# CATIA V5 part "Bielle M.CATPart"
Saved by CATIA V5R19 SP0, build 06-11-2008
Part number: Bielle M
Bounding box of the stored display mesh (mm): x -140 to 140, y -300 to -77.996, z -1349.993 to -50
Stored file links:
  G:\EU_thinkMotion\CFAO_2010\MMS_groupe3\MMS_groupe3\rdalborgo\rdalborgo\Bielle M.CATPart
  G:\EU_thinkMotion\CFAO_2010\MMS_groupe3\MMS_groupe3\rdalborgo\rdalborgo\Bielle P.CATPart
  G:\EU_thinkMotion\CFAO_2010\MMS_groupe3\MMS_groupe3\rdalborgo\rdalborgo\rdalborgo.CATProduct
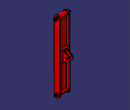
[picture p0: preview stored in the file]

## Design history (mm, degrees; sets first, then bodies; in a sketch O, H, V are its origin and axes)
External parameters (linked from other documents)
  `External.Largeur bielle` = 210 mm
Set1
  Plane1: linked copy from another document
  Point1 "A bielle": linked copy from another document
  Point2 "D bielle": linked copy from another document
  Plane2: linked copy from another document
  Point3 "B verin para": linked copy from another document
  Line1: linked copy from another document
  Point4: linked copy from another document
  Plane3: linked copy from another document
Body1 (main body)
  Sketch1 on Plane1, origin (0, 0, 0), H (0, 1, 0), V (0, 0, 1)
    circle A1 centre (-250, -100) radius 15
    point P1 (-250, -100)
    arc A2 centre (-250, -100) radius 50 from (-200.0003, -99.8329) to (-300, -100) ccw
    point P2 (-250, -100)
    reference projected point E1 (-250, -100) from Point1
    circle A3 centre (-245.9904, -1299.9933) radius 15
    point P3 (-245.9904, -1299.9933)
    point P4 (-245.9904, -1299.9933)
    reference projected point E2 (-245.9904, -1299.9933) from Point2
    line L1 (-300, -100) -> (-295.9904, -1299.9933)
    point P5 (-300, -100)
    line L2 (-195.9904, -1299.9933) -> (-200.0003, -99.8329)
    point P7 (-195.9904, -1299.9933)
    point P8 (-200.0003, -99.8329)
    point P9 (-200.0003, -99.8329)
    arc A4 centre (-245.9904, -1299.9933) radius 50 from (-295.9904, -1299.9933) to (-195.9904, -1299.9933) ccw
    point P10 (-195.9904, -1299.9933)
    radius A1 = 15
    radius A2 = 50
    radius A3 = 15
    radius A4 = 50
    coincidence: P2 P1, P1 E1, P4 P3, P3 E2, P5 A2, P8 A2, P7 P10, P8 P9
    tangency: L2 A2
  Pad1: profile Sketch1, direction (1, 0, 0), length 95, mirrored extent
  Sketch2 on Plane1, origin (0, 0, 0), H (0, 1, 0), V (0, 0, 1)
    arc A1 centre (-250, -100) radius 35 from (-215, -100) to (-260, -133.541) ccw
    point P1 (-250, -100)
    reference projected point E1 (-250, -100) from Point1
    arc A2 centre (-245.9904, -1299.9933) radius 35 from (-210.9904, -1299.9933) to (-240, -1265.5098) ccw
    point P2 (-245.9904, -1299.9933)
    reference projected point E2 (-245.9904, -1299.9933) from Point2
    line L1 (-260, -1267.9194) -> (-260, -133.541)
    point P3 (-260, -1267.9194)
    line L2 (-240, -133.541) -> (-240, -1265.5098)
    point P5 (-240, -133.541)
    point P6 (-240, -1265.5098)
    reference projected point E3 (-250, -100) from Point1
    arc A3 centre (-250, -100) radius 35 from (-240, -133.541) to (-215, -100) ccw
    point P7 (-215, -100)
    point P8 (-215, -100)
    point P9 (-210.9904, -1299.9933)
    point P10 (-210.9904, -1299.9933)
    arc A4 centre (-245.9904, -1299.9933) radius 35 from (-260, -1267.9194) to (-210.9904, -1299.9933) ccw
    radius A1 = 35
    radius A2 = 35
    distance L1 L2 = 20
    distance L1 E3 = 10
    coincidence: P1 E1, P2 E2, P3 A2, P5 A1, P6 A2, A1 A3, P7 P8, P9 P10
    vertical: L1 V, L2 V
  Pocket1: profile Sketch2, direction (-1, 0, 0), length 75, mirrored extent, outer side
  SolidCombine1: FirstComponentProfile Sketch5, FirstComponentDirection Sketch5, SecondComponentProfile Sketch6, SecondComponentDirection Sketch6
  Sketch3 on Plane2, origin (0, 0, 0), H (0, 1, 0), V (0, 0, 1)
    circle A1 centre (-117.9959, -699.5623) radius 10
    point P1 (-117.9959, -699.5623)
    reference projected point E1 (-117.9959, -699.5623) from Point3
    radius A1 = 10
    coincidence: P1 E1
  Pocket2: profile Sketch3, direction (-1, 0, 0), length 105 {= `External.Largeur bielle` /2}, mirrored extent
  Sketch4 on Plane2, origin (0, 0, 0), H (0, 1, 0), V (0, 0, 1)
    circle A1 centre (-250, -100) radius 15
    point P1 (-250, -100)
    circle A2 centre (-250, -100) radius 25
    point P2 (-250, -100)
    circle A3 centre (-245.9904, -1299.9933) radius 15
    circle A4 centre (-245.9904, -1299.9933) radius 25
    point P3 (-245.9904, -1299.9933)
    point P4 (-245.9904, -1299.9933)
    reference projected point E1 (-250, -100) from Point1
    reference projected point E2 (-245.9904, -1299.9933) from Point2
    radius A1 = 15
    radius A2 = 25
    radius A3 = 15
    radius A4 = 25
    coincidence: P2 P1, P4 P3, P2 E1, P4 E2
  Pad2: profile Sketch4, direction (1, 0, 0), length 105 {= `External.Largeur bielle` /2}, mirrored extent
  Sketch5 on Plane3, origin (0, -0.0014, -699.168), H (1, 0, 0), V (0, -1, -0.0033)
    line L1 (75, 197.9952) -> (75, 232.9952)
    line L2 (75, 232.9952) -> (-75, 232.9952)
    line L3 (-75, 232.9952) -> (-75, 197.9952)
    line L4 (-75, 197.9952) -> (-35, 197.9952)
    line L5 (-35, 197.9952) -> (-35, 47.9952)
    line L6 (-35, 47.9952) -> (-20, 47.9952)
    line L7 (-20, 47.9952) -> (-20, 197.9952)
    point P8 (-20, 197.9952)
    line L8 (-20, 197.9952) -> (20, 197.9952)
    line L9 (20, 197.9952) -> (20, 47.9952)
    point P10 (20, 47.9952)
    line L10 (20, 47.9952) -> (35, 47.9952)
    line L11 (35, 47.9952) -> (35, 197.9952)
    point P12 (35, 197.9952)
    line L12 (35, 197.9952) -> (75, 197.9952)
    reference projected point E1 (0, 247.9952) from Point4
    reference projected point E2 (0, 247.9952) from Point4
    reference projected point E3 (0, 247.9952) from Point4
    distance L2 E1 = 15
    distance L2 L12 = 35
    distance L3 L1 = 150 {= `External.Largeur bielle` -60mm}
    distance L3 E2 = 75 {= `External.Largeur bielle` /2-30mm}
    distance L5 L7 = 15
    distance L9 L11 = 15
    distance L6 L8 = 150
    distance L7 L9 = 40
    distance L7 E3 = 20
    vertical: L1 V, L3 V, L5 V, L7 V, L9 V, L11 V
    horizontal: L2 H, L4 H, L6 H, L8 H, L10 H, L12 H
    coincidence: P8 L4, P10 L6, P12 L4
  Sketch6 on Plane2, origin (0, 0, 0), H (0, 1, 0), V (0, 0, 1)
    arc A1 centre (-117.9959, -699.5623) radius 40 from (-77.9959, -699.5623) to (-96.2794, -665.9707) ccw
    point P1 (-117.9959, -699.5623)
    reference projected point E1 (-117.9959, -699.5623) from Point3
    line L1 (-198.3293, -599.9967) -> (-96.2794, -665.9707)
    point P3 (-96.2794, -665.9707)
    line L2 (-198.3293, -599.9967) -> (-233.3293, -599.9967)
    line L3 (-233.3293, -599.9967) -> (-232.661, -799.9967)
    line L4 (-232.661, -799.9967) -> (-197.661, -799.9967)
    line L5 (-197.661, -799.9967) -> (-95.9785, -732.9574)
    point P7 (-95.9785, -732.9574)
    reference projected line E2 (-250, -100) -> (-245.9904, -1299.9933) from Line1
    reference projected point E3 (-247.9952, -699.9967) from Point4
    point P8 (-77.9959, -699.5623)
    point P9 (-77.9959, -699.5623)
    arc A2 centre (-117.9959, -699.5623) radius 40 from (-95.9785, -732.9574) to (-77.9959, -699.5623) ccw
    radius A1 = 40
    distance L3 E2 = 15
    length L4 = 35
    length L2 = 35
    distance L2 L4 = 200
    distance L2 E3 = 100
    coincidence: P1 E1, P3 A1, P7 A1, P8 P9
    tangency: L1 A1, L5 A1
    horizontal: L2 H, L4 H
Body2 "Axe Bielle 1"
  Sketch7 on Plane1, origin (0, 0, 0), H (0, 1, 0), V (0, 0, 1)
    circle A1 centre (-250, -100) radius 15
    point P1 (-250, -100)
    reference projected point E1 (-250, -100) from Point1
    radius A1 = 15
    coincidence: P1 E1
  Pad3: profile Sketch7, direction (1, 0, 0), length 125 {= `External.Largeur bielle` /2+20mm}, mirrored extent
  Sketch8 on start face of Pad3, origin (-125, 0, 0), H (0, -1, 0), V (0, 0, 1)
    circle A1 centre (250, -100) radius 20
    point P1 (250, -100)
    reference projected point E1 (250, -100) from Point1
    radius A1 = 20
    coincidence: P1 E1
  Pad4: profile Sketch8, direction (-1, 0, 0), length 5
  Sketch9 on end face of Pad4, origin (-130, 0, 0), H (0, -1, 0), V (0, 0, 1)
    point P1 (250, -100)
    point P2 (241.3397, -115)
    point P3 (258.6603, -115)
    point P4 (267.3205, -100)
    point P5 (258.6603, -85)
    point P6 (241.3397, -85)
    point P7 (232.6795, -100)
    point P8 (250, -115)
    line L1 (241.3397, -115) -> (258.6603, -115)
    line L2 (258.6603, -115) -> (267.3205, -100)
    line L3 (267.3205, -100) -> (258.6603, -85)
    line L4 (258.6603, -85) -> (241.3397, -85)
    line L5 (241.3397, -85) -> (232.6795, -100)
    line L6 (232.6795, -100) -> (241.3397, -115)
    construction line L7 (250, -100) -> (250, -115)
    construction circle A1 centre (250, -100) radius 17.3205
    construction arc A2 centre (241.3397, -85) radius 17.3205 from (258.6603, -85) to (232.6795, -100) cw
    construction arc A3 centre (258.6603, -115) radius 17.3205 from (267.3205, -100) to (241.3397, -115) ccw
    reference projected point E1 (250, -100) from Point1
    distance L1 L4 = 30
    vertical: L7 V
    coincidence: A1 P2, A1 P3, A1 P4, A1 P5, A1 P6, A1 P7, A2 P1, A3 P1, P1 E1
    midpoint: P8 L1
  Pad5: profile Sketch9, direction (-1, 0, 0), length 10
  Sketch10 on end face of Pad3, origin (125, 0, 0), H (0, 1, 0), V (0, 0, 1)
    circle A1 centre (-250, -100) radius 10
    point P1 (-250, -100)
    reference projected point E1 (-250, -100) from Point1
    radius A1 = 10
    coincidence: P1 E1
  Pad6: profile Sketch10, direction (1, 0, 0), length 15
  Sketch11 on end face of Pad3, origin (125, 0, 0), H (0, 1, 0), V (0, 0, 1)
    circle A1 centre (-250, -100) radius 10
    point P1 (-250, -100)
    circle A2 centre (-250, -100) radius 20
    point P2 (-250, -100)
    reference projected point E1 (-250, -100) from Point1
    radius A1 = 10
    radius A2 = 20
    coincidence: P2 P1, P2 E1
  Pad7: profile Sketch11, direction (1, 0, 0), length 5
  Sketch12 on end face of Pad7, origin (130, 0, 0), H (0, 1, 0), V (0, 0, 1)
    point P1 (-250, -100)
    point P2 (-244.6378, -116.4696)
    point P3 (-233.0558, -103.591)
    point P4 (-238.418, -87.1214)
    point P5 (-255.3622, -83.5304)
    point P6 (-266.9442, -96.409)
    point P7 (-261.582, -112.8786)
    point P8 (-238.8468, -110.0303)
    line L1 (-244.6378, -116.4696) -> (-233.0558, -103.591)
    line L2 (-233.0558, -103.591) -> (-238.418, -87.1214)
    line L3 (-238.418, -87.1214) -> (-255.3622, -83.5304)
    line L4 (-255.3622, -83.5304) -> (-266.9442, -96.409)
    line L5 (-266.9442, -96.409) -> (-261.582, -112.8786)
    line L6 (-261.582, -112.8786) -> (-244.6378, -116.4696)
    construction line L7 (-250, -100) -> (-238.8468, -110.0303)
    construction circle A1 centre (-250, -100) radius 17.3205
    construction arc A2 centre (-266.9442, -96.409) radius 17.3205 from (-255.3622, -83.5304) to (-261.582, -112.8786) cw
    construction arc A3 centre (-233.0558, -103.591) radius 17.3205 from (-238.418, -87.1214) to (-244.6378, -116.4696) ccw
    reference projected point E1 (-250, -100) from Point1
    circle A4 centre (-250, -100) radius 10
    point P9 (-250, -100)
    reference projected point E2 (-250, -100) from Point1
    distance L3 L6 = 30
    radius A4 = 10
    coincidence: A1 P2, A1 P3, A1 P4, A1 P5, A1 P6, A1 P7, A2 P1, A3 P1, P1 E1, P9 E2
    midpoint: P8 L1
    parallelism: L1 L4
  Pad8: profile Sketch12, direction (1, 0, 0), length 8
Body3 "Axe Bielle 2"
  Sketch13 on Plane1, origin (0, 0, 0), H (0, 1, 0), V (0, 0, 1)
    circle A1 centre (-245.9904, -1299.9933) radius 15
    point P1 (-245.9904, -1299.9933)
    reference projected point E1 (-245.9904, -1299.9933) from Point2
    radius A1 = 15
    coincidence: P1 E1
  Pad9: profile Sketch13, direction (1, 0, 0), length 120 {= `External.Largeur bielle` /2+15mm}, mirrored extent
  Sketch14 on start face of Pad9, origin (-120, 0, 0), H (0, -1, 0), V (0, 0, 1)
    circle A1 centre (245.9904, -1299.9933) radius 20
    point P1 (245.9904, -1299.9933)
    reference projected point E1 (245.9904, -1299.9933) from Point2
    radius A1 = 20
    coincidence: P1 E1
  Pad10: profile Sketch14, direction (-1, 0, 0), length 5
  Sketch15 on end face of Pad10, origin (-125, 0, 0), H (0, -1, 0), V (0, 0, 1)
    point P1 (245.9904, -1299.9933)
    point P2 (237.3302, -1314.9933)
    point P3 (254.6507, -1314.9933)
    point P4 (263.3109, -1299.9933)
    point P5 (254.6507, -1284.9933)
    point P6 (237.3302, -1284.9933)
    point P7 (228.6699, -1299.9933)
    point P8 (245.9904, -1314.9933)
    line L1 (237.3302, -1314.9933) -> (254.6507, -1314.9933)
    line L2 (254.6507, -1314.9933) -> (263.3109, -1299.9933)
    line L3 (263.3109, -1299.9933) -> (254.6507, -1284.9933)
    line L4 (254.6507, -1284.9933) -> (237.3302, -1284.9933)
    line L5 (237.3302, -1284.9933) -> (228.6699, -1299.9933)
    line L6 (228.6699, -1299.9933) -> (237.3302, -1314.9933)
    construction line L7 (245.9904, -1299.9933) -> (245.9904, -1314.9933)
    construction circle A1 centre (245.9904, -1299.9933) radius 17.3205
    construction arc A2 centre (237.3302, -1284.9933) radius 17.3205 from (254.6507, -1284.9933) to (228.6699, -1299.9933) cw
    construction arc A3 centre (254.6507, -1314.9933) radius 17.3205 from (263.3109, -1299.9933) to (237.3302, -1314.9933) ccw
    reference projected point E1 (245.9904, -1299.9933) from Point2
    distance L1 L4 = 30
    vertical: L7 V
    coincidence: A1 P2, A1 P3, A1 P4, A1 P5, A1 P6, A1 P7, A2 P1, A3 P1, P1 E1
    midpoint: P8 L1
  Pad11: profile Sketch15, direction (-1, 0, 0), length 10
  Sketch16 on end face of Pad9, origin (120, 0, 0), H (0, 1, 0), V (0, 0, 1)
    circle A1 centre (-245.9904, -1299.9933) radius 10
    point P1 (-245.9904, -1299.9933)
    reference projected point E1 (-245.9904, -1299.9933) from Point2
    radius A1 = 10
    coincidence: P1 E1
  Pad12: profile Sketch16, direction (1, 0, 0), length 15
  Sketch17 on end face of Pad9, origin (120, 0, 0), H (0, 1, 0), V (0, 0, 1)
    circle A1 centre (-245.9904, -1299.9933) radius 10
    point P1 (-245.9904, -1299.9933)
    circle A2 centre (-245.9904, -1299.9933) radius 20
    point P2 (-245.9904, -1299.9933)
    reference projected point E1 (-245.9904, -1299.9933) from Point2
    radius A1 = 10
    radius A2 = 20
    coincidence: P2 P1, P2 E1
  Pad13: profile Sketch17, direction (1, 0, 0), length 5
  Sketch18 on end face of Pad13, origin (125, 0, 0), H (0, 1, 0), V (0, 0, 1)
    point P1 (-245.9904, -1299.9933)
    point P2 (-240.6283, -1316.4629)
    point P3 (-229.0463, -1303.5843)
    point P4 (-234.4085, -1287.1147)
    point P5 (-251.3526, -1283.5237)
    point P6 (-262.9346, -1296.4023)
    point P7 (-257.5724, -1312.8719)
    point P8 (-234.8373, -1310.0236)
    line L1 (-240.6283, -1316.4629) -> (-229.0463, -1303.5843)
    line L2 (-229.0463, -1303.5843) -> (-234.4085, -1287.1147)
    line L3 (-234.4085, -1287.1147) -> (-251.3526, -1283.5237)
    line L4 (-251.3526, -1283.5237) -> (-262.9346, -1296.4023)
    line L5 (-262.9346, -1296.4023) -> (-257.5724, -1312.8719)
    line L6 (-257.5724, -1312.8719) -> (-240.6283, -1316.4629)
    construction line L7 (-245.9904, -1299.9933) -> (-234.8373, -1310.0236)
    construction circle A1 centre (-245.9904, -1299.9933) radius 17.3205
    construction arc A2 centre (-262.9346, -1296.4023) radius 17.3205 from (-251.3526, -1283.5237) to (-257.5724, -1312.8719) cw
    construction arc A3 centre (-229.0463, -1303.5843) radius 17.3205 from (-234.4085, -1287.1147) to (-240.6283, -1316.4629) ccw
    reference projected point E1 (-245.9904, -1299.9933) from Point2
    circle A4 centre (-245.9904, -1299.9933) radius 10
    point P9 (-245.9904, -1299.9933)
    reference projected point E2 (-245.9904, -1299.9933) from Point2
    distance L3 L6 = 30
    radius A4 = 10
    coincidence: A1 P2, A1 P3, A1 P4, A1 P5, A1 P6, A1 P7, A2 P1, A3 P1, P1 E1, P9 E2
    midpoint: P8 L1
    parallelism: L1 L4
  Pad14: profile Sketch18, direction (1, 0, 0), length 8
Body4 "Axe verin"
  Sketch19 on Plane1, origin (0, 0, 0), H (0, 1, 0), V (0, 0, 1)
    circle A1 centre (-117.9959, -699.5623) radius 10
    point P1 (-117.9959, -699.5623)
    reference projected point E1 (-117.9959, -699.5623) from Point3
    radius A1 = 10
    coincidence: E1 P1
  Pad15: profile Sketch19, direction (1, 0, 0), length 35, mirrored extent
  Sketch20 on start face of Pad15, origin (-35, 0, 0), H (0, -1, 0), V (0, 0, 1)
    circle A1 centre (117.9959, -699.5623) radius 15
    point P1 (117.9959, -699.5623)
    reference projected point E1 (117.9959, -699.5623) from Point3
    radius A1 = 15
    coincidence: P1 E1
  Pad16: profile Sketch20, direction (-1, 0, 0), length 5
  Sketch21 on end face of Pad16, origin (-40, 0, 0), H (0, -1, 0), V (0, 0, 1)
    point P1 (117.9959, -699.5623)
    point P2 (121.2834, -711.8312)
    point P3 (130.2649, -702.8497)
    point P4 (126.9774, -690.5808)
    point P5 (114.7085, -687.2934)
    point P6 (105.727, -696.2748)
    point P7 (109.0145, -708.5437)
    point P8 (125.7741, -707.3405)
    line L1 (121.2834, -711.8312) -> (130.2649, -702.8497)
    line L2 (130.2649, -702.8497) -> (126.9774, -690.5808)
    line L3 (126.9774, -690.5808) -> (114.7085, -687.2934)
    line L4 (114.7085, -687.2934) -> (105.727, -696.2748)
    line L5 (105.727, -696.2748) -> (109.0145, -708.5437)
    line L6 (109.0145, -708.5437) -> (121.2834, -711.8312)
    construction line L7 (117.9959, -699.5623) -> (125.7741, -707.3405)
    construction circle A1 centre (117.9959, -699.5623) radius 12.7017
    construction arc A2 centre (105.727, -696.2748) radius 12.7017 from (114.7085, -687.2934) to (109.0145, -708.5437) cw
    construction arc A3 centre (130.2649, -702.8497) radius 12.7017 from (126.9774, -690.5808) to (121.2834, -711.8312) ccw
    reference projected point E1 (117.9959, -699.5623) from Point3
    distance L3 L6 = 22
    coincidence: A1 P2, A1 P3, A1 P4, A1 P5, A1 P6, A1 P7, A2 P1, A3 P1, P1 E1
    midpoint: P8 L1
    parallelism: L1 L4
  Pad17: profile Sketch21, direction (-1, 0, 0), length 8
  Sketch22 on end face of Pad15, origin (35, 0, 0), H (0, 1, 0), V (0, 0, 1)
    circle A1 centre (-117.9959, -699.5623) radius 7.5
    point P1 (-117.9959, -699.5623)
    reference projected point E1 (-117.9959, -699.5623) from Point3
    radius A1 = 7.5
    coincidence: P1 E1
  Pad18: profile Sketch22, direction (1, 0, 0), length 12
  Sketch23 on end face of Pad15, origin (35, 0, 0), H (0, 1, 0), V (0, 0, 1)
    circle A1 centre (-117.9959, -699.5623) radius 12.5
    point P1 (-117.9959, -699.5623)
    circle A2 centre (-117.9959, -699.5623) radius 7.5
    reference projected point E1 (-117.9959, -699.5623) from Point3
    radius A1 = 12.5
    radius A2 = 7.5
    coincidence: P1 E1
  Pad19: profile Sketch23, direction (1, 0, 0), length 3
  Sketch24 on end face of Pad19, origin (38, 0, 0), H (0, 1, 0), V (0, 0, 1)
    point P1 (-117.9959, -699.5623)
    point P2 (-112.9064, -689.1975)
    point P3 (-124.4274, -689.9722)
    point P4 (-129.5169, -700.337)
    point P5 (-123.0855, -709.9271)
    point P6 (-111.5645, -709.1524)
    point P7 (-106.475, -698.7876)
    point P8 (-118.6669, -689.5848)
    line L1 (-112.9064, -689.1975) -> (-124.4274, -689.9722)
    line L2 (-124.4274, -689.9722) -> (-129.5169, -700.337)
    line L3 (-129.5169, -700.337) -> (-123.0855, -709.9271)
    line L4 (-123.0855, -709.9271) -> (-111.5645, -709.1524)
    line L5 (-111.5645, -709.1524) -> (-106.475, -698.7876)
    line L6 (-106.475, -698.7876) -> (-112.9064, -689.1975)
    construction line L7 (-117.9959, -699.5623) -> (-118.6669, -689.5848)
    construction circle A1 centre (-117.9959, -699.5623) radius 11.547
    construction arc A2 centre (-111.5645, -709.1524) radius 11.547 from (-123.0855, -709.9271) to (-106.475, -698.7876) cw
    construction arc A3 centre (-124.4274, -689.9722) radius 11.547 from (-129.5169, -700.337) to (-112.9064, -689.1975) ccw
    reference projected point E1 (-117.9959, -699.5623) from Point3
    circle A4 centre (-117.9959, -699.5623) radius 7.5
    point P9 (-117.9959, -699.5623)
    reference projected point E2 (-117.9959, -699.5623) from Point3
    distance L1 L4 = 20
    radius A4 = 7.5
    coincidence: A1 P2, A1 P3, A1 P4, A1 P5, A1 P6, A1 P7, A2 P1, A3 P1, P1 E1, P9 E2
    midpoint: P8 L1
  Pad20: profile Sketch24, direction (1, 0, 0), length 8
